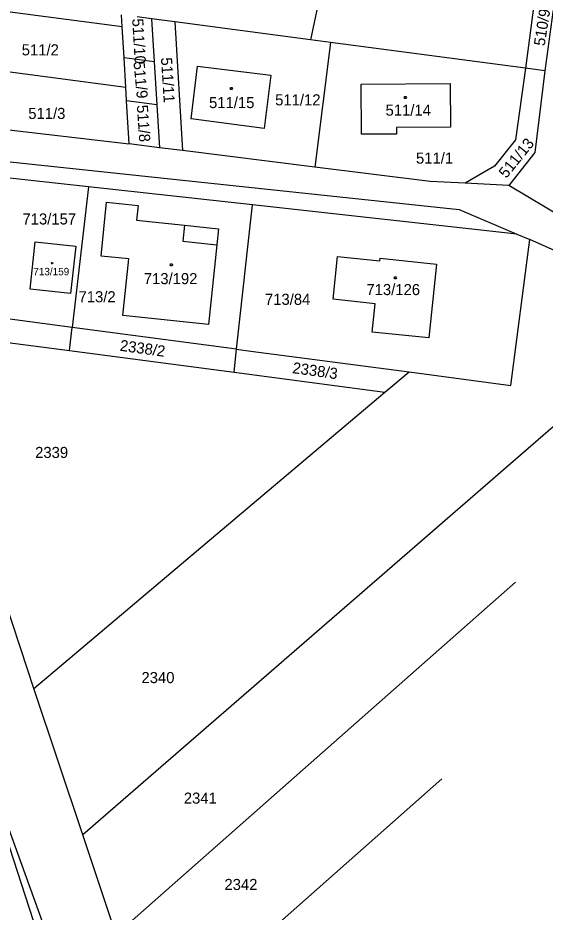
# Model space of a CAD drawing. Extents: x -639590 to -639298, y -1193269 to -1192863.
# Drawn here: x -639476.5 to -639395.8, y -1193132.4 to -1192995.4 of the extents above; entities that cross this region are included whole.
import ezdxf

# ---------------------------------------------------------------- set-up
doc = ezdxf.new("R2010")
doc.units = 0
for name, color, linetype in [('Vrstva 1', 7, 'Continuous'), ('Vrstva 2', 7, 'Continuous'), ('Vrstva 22', 7, 'Continuous'), ('Vrstva 4', 7, 'Continuous'), ('Vrstva 5', 7, 'Continuous')]:
    doc.layers.add(name, color=color, linetype=linetype)

msp = doc.modelspace()

# ---------------------------------------------------------------- linework, layer by layer
at = {"layer": 'Vrstva 1'}
for p, q in [((-639396.4, -1192985.25), (-639398.77, -1193003.07)), ((-639393.41, -1192985.63), (-639395.79, -1193003.46)), ((-639460.55, -1192996.75), (-639483.21, -1192993.78)), ((-639430.58, -1192993.42), (-639431.72, -1192998.71)), ((-639460.55, -1192996.75), (-639460.66, -1192994.89)), ((-639456.03, -1192995.5), (-639458.26, -1192995.21)), ((-639456.03, -1192995.5), (-639455.63, -1193002.09)), ((-639452.5, -1192995.97), (-639456.03, -1192995.5)), ((-639431.72, -1192998.71), (-639452.5, -1192995.97)), ((-639452.5, -1192995.97), (-639451.31, -1193015.69)), ((-639460.26, -1193001.5), (-639460.55, -1192996.75)), ((-639428.65, -1192999.12), (-639431.72, -1192998.71)), ((-639428.65, -1192999.12), (-639431.01, -1193018.22)), ((-639398.77, -1193003.07), (-639428.65, -1192999.12)), ((-639455.63, -1193002.09), (-639460.26, -1193001.5)), ((-639459.99, -1193005.96), (-639460.26, -1193001.5)), ((-639455.63, -1193002.09), (-639455.23, -1193008.67)), ((-639449.98, -1193010.83), (-639449.03, -1193002.74)), ((-639449.03, -1193002.74), (-639437.79, -1193004.15)), ((-639482.56, -1193002.99), (-639459.99, -1193005.96)), ((-639437.79, -1193004.15), (-639438.81, -1193012.29)), ((-639398.77, -1193003.07), (-639400.28, -1193014.04)), ((-639395.79, -1193003.46), (-639398.77, -1193003.07)), ((-639395.79, -1193003.46), (-639397.35, -1193015.99)), ((-639423.92, -1193005.5), (-639410.3, -1193005.42)), ((-639423.88, -1193013.19), (-639423.92, -1193005.5)), ((-639410.3, -1193005.42), (-639410.26, -1193012.08)), ((-639459.86, -1193008.08), (-639459.99, -1193005.96)), ((-639459.46, -1193014.67), (-639459.86, -1193008.08)), ((-639455.23, -1193008.67), (-639459.86, -1193008.08)), ((-639455.23, -1193008.67), (-639454.83, -1193015.25)), ((-639438.81, -1193012.29), (-639449.98, -1193010.83)), ((-639483.54, -1193011.82), (-639459.46, -1193014.67)), ((-639410.26, -1193012.08), (-639418.51, -1193012.16)), ((-639418.51, -1193012.16), (-639418.5, -1193013.15)), ((-639418.5, -1193013.15), (-639423.88, -1193013.19)), ((-639501.94, -1193014.81), (-639408.9, -1193024.71)), ((-639454.83, -1193015.25), (-639459.46, -1193014.67)), ((-639400.28, -1193014.04), (-639403.51, -1193018.07)), ((-639451.31, -1193015.69), (-639454.83, -1193015.25)), ((-639431.01, -1193018.22), (-639451.31, -1193015.69)), ((-639397.35, -1193015.99), (-639401.32, -1193021.01)), ((-639465.69, -1193021.25), (-639501.06, -1193017.35)), ((-639413.38, -1193020.42), (-639431.01, -1193018.22)), ((-639403.51, -1193018.07), (-639407.99, -1193020.68)), ((-639407.99, -1193020.68), (-639413.38, -1193020.42)), ((-639465.69, -1193021.25), (-639468.21, -1193042.77)), ((-639440.59, -1193024.01), (-639465.69, -1193021.25)), ((-639401.32, -1193021.01), (-639407.99, -1193020.68)), ((-639391.81, -1193026.72), (-639401.32, -1193021.01)), ((-639463.78, -1193031.84), (-639462.92, -1193023.59)), ((-639462.92, -1193023.59), (-639458.1, -1193024.1)), ((-639458.1, -1193024.1), (-639458.33, -1193026.34)), ((-639443.02, -1193046.1), (-639440.59, -1193024.01)), ((-639400.07, -1193028.47), (-639440.59, -1193024.01)), ((-639408.9, -1193024.71), (-639400.07, -1193028.47)), ((-639458.33, -1193026.34), (-639451.01, -1193027.12)), ((-639451.01, -1193027.12), (-639445.77, -1193027.68)), ((-639445.77, -1193027.68), (-639446.03, -1193030.1)), ((-639400.07, -1193028.47), (-639398.1, -1193029.3)), ((-639474.65, -1193036.9), (-639473.85, -1193029.69)), ((-639473.85, -1193029.69), (-639467.63, -1193030.32)), ((-639446.03, -1193030.1), (-639447.34, -1193042.34)), ((-639401, -1193051.65), (-639398.1, -1193029.3)), ((-639394.21, -1193031.06), (-639398.1, -1193029.3)), ((-639467.63, -1193030.32), (-639468.48, -1193037.59)), ((-639459.53, -1193032.26), (-639463.78, -1193031.84)), ((-639460.42, -1193040.96), (-639459.53, -1193032.26)), ((-639428.2, -1193038.43), (-639427.54, -1193031.91)), ((-639427.54, -1193031.91), (-639421.06, -1193032.6)), ((-639421.06, -1193032.6), (-639421.02, -1193032.17)), ((-639421.02, -1193032.17), (-639412.39, -1193033.08)), ((-639412.39, -1193033.08), (-639413.59, -1193044.39)), ((-639468.48, -1193037.59), (-639474.65, -1193036.9)), ((-639421.77, -1193039.15), (-639428.2, -1193038.43)), ((-639468.21, -1193042.77), (-639493.42, -1193039.43)), ((-639422.23, -1193043.48), (-639421.77, -1193039.15)), ((-639447.34, -1193042.34), (-639460.42, -1193040.96)), ((-639492.18, -1193043.2), (-639468.63, -1193046.32)), ((-639468.63, -1193046.32), (-639468.21, -1193042.77)), ((-639443.02, -1193046.1), (-639468.21, -1193042.77)), ((-639377.41, -1193043.16), (-639466.59, -1193120.49)), ((-639413.59, -1193044.39), (-639422.23, -1193043.48)), ((-639468.63, -1193046.32), (-639443.41, -1193049.65)), ((-639443.41, -1193049.65), (-639443.02, -1193046.1)), ((-639443.02, -1193046.1), (-639440.82, -1193046.39)), ((-639440.82, -1193046.39), (-639416.6, -1193049.59)), ((-639443.41, -1193049.65), (-639420.3, -1193052.71)), ((-639420.3, -1193052.71), (-639416.6, -1193049.59)), ((-639416.6, -1193049.59), (-639401, -1193051.65)), ((-639474.06, -1193098.11), (-639420.3, -1193052.71)), ((-639475.06, -1193095.11), (-639479.86, -1193080.55)), ((-639400.3, -1193081.78), (-639461.48, -1193135.8)), ((-639474.06, -1193098.11), (-639475.06, -1193095.11)), ((-639486.01, -1193097.33), (-639448.4, -1193212.6)), ((-639466.59, -1193120.49), (-639474.06, -1193098.11)), ((-639411.59, -1193111.93), (-639456.25, -1193151.46)), ((-639461.48, -1193135.8), (-639466.59, -1193120.49))]:
    msp.add_line(p, q, dxfattribs=at)
at = {"layer": 'Vrstva 22'}
msp.add_lwpolyline([(-639450.45, -1193202.7), (-639464.28, -1193158.66), (-639472.09, -1193135.67), (-639482.36, -1193107.37)], dxfattribs=at)
at = {"layer": 'Vrstva 4'}
for p, q in [((-639451.01, -1193027.12), (-639451.27, -1193029.54)), ((-639451.27, -1193029.54), (-639446.03, -1193030.1))]:
    msp.add_line(p, q, dxfattribs=at)
at = {"layer": 'Vrstva 5'}
for points in [[(-639443.73, -1193006.03), (-639443.64, -1193006.18), (-639443.73, -1193006.33), (-639443.91, -1193006.33), (-639444, -1193006.18), (-639443.91, -1193006.03)], [(-639417.07, -1193007.4), (-639416.98, -1193007.55), (-639417.07, -1193007.7), (-639417.25, -1193007.7), (-639417.34, -1193007.55), (-639417.25, -1193007.4)], [(-639471.22, -1193032.83), (-639471.16, -1193032.93), (-639471.22, -1193033.03), (-639471.34, -1193033.03), (-639471.4, -1193032.93), (-639471.34, -1193032.83)], [(-639452.9, -1193033.05), (-639452.81, -1193033.2), (-639452.9, -1193033.35), (-639453.08, -1193033.35), (-639453.17, -1193033.2), (-639453.08, -1193033.05)], [(-639418.62, -1193035.02), (-639418.53, -1193035.17), (-639418.62, -1193035.32), (-639418.8, -1193035.32), (-639418.89, -1193035.17), (-639418.8, -1193035.02)]]:
    msp.add_lwpolyline(points, close=True, dxfattribs=at)

# ---------------------------------------------------------------- texts
at = {"layer": 'Vrstva 2'}
for s, rotation, p in [('510/9', 81.1308, (-639395.83, -1192999.74)), ('511/10', 273.4728, (-639459.02, -1192995.5)), ('511/9', 275.3062, (-639458.81, -1193002.11)), ('511/11', 273.7019, (-639454.61, -1193001.46)), ('511/8', 273.9884, (-639458.31, -1193008.75)), ('511/13', 51.0505, (-639401.7, -1193020.04)), ('2338/2', 352.1399, (-639460.97, -1193046.34)), ('2338/3', 352.1399, (-639434.54, -1193049.77))]:
    msp.add_text(s, height=1.7, rotation=rotation, dxfattribs=at).set_placement(p)
for s, height, p in [('511/2', 1.7, (-639475.93, -1193001.1)), ('511/15', 1.7, (-639447.24, -1193009.18)), ('511/12', 1.7, (-639437.11, -1193008.76)), ('511/3', 1.7, (-639474.93, -1193010.84)), ('511/14', 1.7, (-639420.2, -1193010.34)), ('511/1', 1.7, (-639415.54, -1193017.69)), ('713/157', 1.7, (-639475.82, -1193027.01)), ('713/159', 1.14, (-639474.16, -1193034.79)), ('713/192', 1.7, (-639457.23, -1193036.15)), ('713/126', 1.7, (-639423.13, -1193037.83)), ('713/2', 1.7, (-639467.23, -1193038.93)), ('713/84', 1.7, (-639438.67, -1193039.32)), ('2339', 1.7, (-639473.88, -1193062.78)), ('2340', 1.7, (-639457.59, -1193097.27)), ('2341', 1.7, (-639451.1, -1193115.74)), ('2342', 1.7, (-639444.88, -1193128.97))]:
    msp.add_text(s, height=height, dxfattribs=at).set_placement(p)

doc.saveas('drawing.dxf')
